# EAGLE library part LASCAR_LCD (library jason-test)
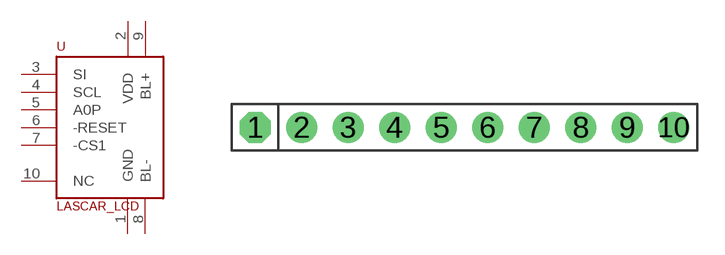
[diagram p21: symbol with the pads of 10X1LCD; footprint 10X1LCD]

Designator prefix -

## LASCAR_LCD  [10X1LCD]
1  GND  pwr
2  VDD  pwr
3  SI
4  SCL  in
5  A0P  in
6  -RESET  in
7  -CS1  in
8  BL-  pwr
9  BL+  pwr
10  NC  pas

## Footprint 10X1LCD (pad centres in mm)
drill 1 pad 1.676 octagon: 1 -11.43,0
drill 1 pad 1.676 round: 2 -8.89,0; 3 -6.35,0; 4 -3.81,0; 5 -1.27,0; 6 1.27,0; 7 3.81,0; 8 6.35,0; 9 8.89,0; 10 11.43,0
